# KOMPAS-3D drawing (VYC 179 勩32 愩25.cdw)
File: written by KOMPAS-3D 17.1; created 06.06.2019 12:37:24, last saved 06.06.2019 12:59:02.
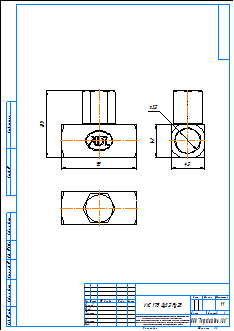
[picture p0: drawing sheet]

Sheet 1: A3, portrait

Title block, sheet 1: name: VYC 179 Ду32 Ру25; material: Внимание! Данный продукт является объектом авторского права ООО «Торговый Дом АДЛ». / Запрещается изменение, копирование, распространение / (в том числе путем копирования на другие сайты и ресурсы в Интернете) / или любое иное использование информации и объектов без предварительного / согласия правообладателя (ООО «Торговый Дом АДЛ»).; sheets: 1; organisation: ООО "Торговый дом АДЛ"; sheet format: A3; stored path: \\adlc.lan\data\АДЛ_ПКД\3D-модели\Поставщики\VYC Industrial\VYC 179\KOMPAS 2D\VYC 179 Ду32 Ру25.cdw

Views: Вид 1, Проекционный вид 2, Проекционный вид 3
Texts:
  user
Dimensions and other numbers on the sheet: 95; 85; 42; 32; 1:1; 1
